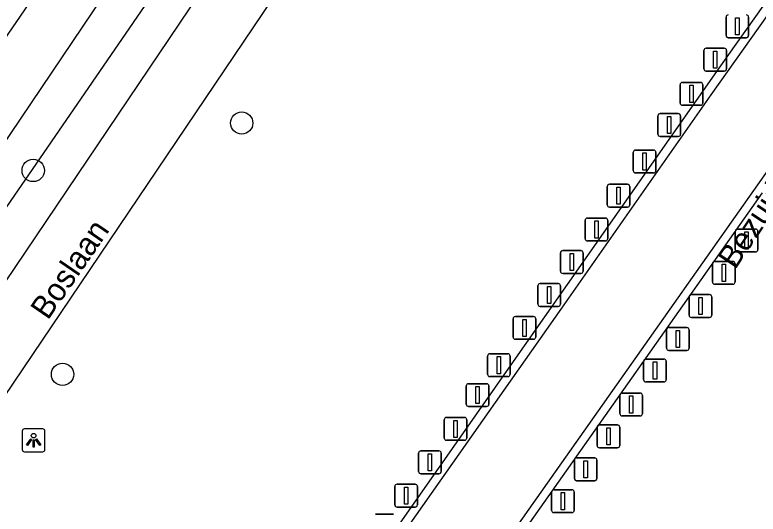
# Model space of a CAD drawing. Extents: x 157154 to 159278, y 385000 to 386650.
# Drawn here: x 159128.11 to 159160.66, y 385103.26 to 385125.13 of the extents above; entities that cross this region are included whole.
import ezdxf

# ---------------------------------------------------------------- set-up
doc = ezdxf.new("R2010")
doc.units = 0
for name, color, linetype in [('IMGEO_Afsluitpaal', 7, 'Continuous'), ('IMGEO_Boom', 7, 'Continuous'), ('IMGEO_Grasland_overig', 7, 'Continuous'), ('IMGEO_Lichtpunt', 7, 'Continuous'), ('IMGEO_Openbare_ruimte_label', 7, 'Continuous'), ('IMGEO_Rijbaan_lokaal_gesloten', 7, 'Continuous'), ('IMGEO_Rijbaan_lokaal_halfverhard', 7, 'Continuous'), ('IMGEO_Voetpad_halfverhard', 7, 'Continuous'), ('IMGEO_Waterloop', 7, 'Continuous')]:
    doc.layers.add(name, color=color, linetype=linetype)

msp = doc.modelspace()

# ---------------------------------------------------------------- linework, layer by layer
at = {"layer": 'IMGEO_Afsluitpaal'}
for p, q in [((159159.252, 385124.235), (159159.252, 385125.035)), ((159159.252, 385125.035), (159159.252, 385124.235)), ((159160.242, 385125.035), (159160.242, 385124.235)), ((159160.242, 385124.235), (159160.242, 385125.035)), ((159160.142, 385124.135), (159159.352, 385124.135)), ((159159.352, 385124.135), (159160.142, 385124.135)), ((159158.283, 385122.773), (159158.283, 385123.573)), ((159158.283, 385123.573), (159158.283, 385122.773)), ((159158.383, 385123.673), (159159.173, 385123.673)), ((159159.173, 385123.673), (159158.383, 385123.673)), ((159159.273, 385123.573), (159159.273, 385122.773)), ((159159.273, 385122.773), (159159.273, 385123.573)), ((159159.173, 385122.673), (159158.383, 385122.673)), ((159158.383, 385122.673), (159159.173, 385122.673)), ((159157.339, 385122.173), (159158.129, 385122.173)), ((159158.129, 385122.173), (159157.339, 385122.173)), ((159157.239, 385121.273), (159157.239, 385122.073)), ((159157.239, 385122.073), (159157.239, 385121.273)), ((159158.229, 385122.073), (159158.229, 385121.273)), ((159158.229, 385121.273), (159158.229, 385122.073)), ((159158.129, 385121.173), (159157.339, 385121.173)), ((159157.339, 385121.173), (159158.129, 385121.173)), ((159156.271, 385119.906), (159156.271, 385120.706)), ((159156.271, 385120.706), (159156.271, 385119.906)), ((159156.371, 385120.806), (159157.161, 385120.806)), ((159157.161, 385120.806), (159156.371, 385120.806)), ((159157.261, 385120.706), (159157.261, 385119.906)), ((159157.261, 385119.906), (159157.261, 385120.706)), ((159157.161, 385119.806), (159156.371, 385119.806)), ((159156.371, 385119.806), (159157.161, 385119.806)), ((159155.188, 385118.311), (159155.188, 385119.111)), ((159155.188, 385119.111), (159155.188, 385118.311)), ((159155.288, 385119.211), (159156.078, 385119.211)), ((159156.078, 385119.211), (159155.288, 385119.211)), ((159156.178, 385119.111), (159156.178, 385118.311)), ((159156.178, 385118.311), (159156.178, 385119.111)), ((159156.078, 385118.211), (159155.288, 385118.211)), ((159155.288, 385118.211), (159156.078, 385118.211)), ((159154.049, 385116.811), (159154.049, 385117.611)), ((159154.049, 385117.611), (159154.049, 385116.811)), ((159154.149, 385117.711), (159154.939, 385117.711)), ((159154.939, 385117.711), (159154.149, 385117.711)), ((159155.039, 385117.611), (159155.039, 385116.811)), ((159155.039, 385116.811), (159155.039, 385117.611)), ((159154.939, 385116.711), (159154.149, 385116.711)), ((159154.149, 385116.711), (159154.939, 385116.711)), ((159153.081, 385115.33), (159153.081, 385116.13)), ((159153.081, 385116.13), (159153.081, 385115.33)), ((159153.181, 385116.23), (159153.971, 385116.23)), ((159153.971, 385116.23), (159153.181, 385116.23)), ((159154.071, 385116.13), (159154.071, 385115.33)), ((159154.071, 385115.33), (159154.071, 385116.13)), ((159159.656, 385114.848), (159159.656, 385115.648)), ((159159.656, 385115.648), (159159.656, 385114.848)), ((159159.756, 385115.748), (159160.546, 385115.748)), ((159160.546, 385115.748), (159159.756, 385115.748)), ((159160.646, 385115.648), (159160.646, 385114.848)), ((159160.646, 385114.848), (159160.646, 385115.648)), ((159153.971, 385115.23), (159153.181, 385115.23)), ((159153.181, 385115.23), (159153.971, 385115.23)), ((159151.999, 385113.906), (159151.999, 385114.706)), ((159151.999, 385114.706), (159151.999, 385113.906)), ((159152.099, 385114.806), (159152.889, 385114.806)), ((159152.889, 385114.806), (159152.099, 385114.806)), ((159152.989, 385114.706), (159152.989, 385113.906)), ((159152.989, 385113.906), (159152.989, 385114.706)), ((159160.546, 385114.748), (159159.756, 385114.748)), ((159159.756, 385114.748), (159160.546, 385114.748)), ((159158.658, 385113.432), (159158.658, 385114.232)), ((159158.658, 385114.232), (159158.658, 385113.432)), ((159158.758, 385114.332), (159159.548, 385114.332)), ((159159.548, 385114.332), (159158.758, 385114.332)), ((159159.648, 385114.232), (159159.648, 385113.432)), ((159159.648, 385113.432), (159159.648, 385114.232)), ((159152.889, 385113.806), (159152.099, 385113.806)), ((159152.099, 385113.806), (159152.889, 385113.806)), ((159151.011, 385112.463), (159151.011, 385113.263)), ((159151.011, 385113.263), (159151.011, 385112.463)), ((159151.111, 385113.363), (159151.901, 385113.363)), ((159151.901, 385113.363), (159151.111, 385113.363)), ((159152.001, 385113.263), (159152.001, 385112.463)), ((159152.001, 385112.463), (159152.001, 385113.263)), ((159159.548, 385113.332), (159158.758, 385113.332)), ((159158.758, 385113.332), (159159.548, 385113.332)), ((159157.635, 385111.977), (159157.635, 385112.777)), ((159157.635, 385112.777), (159157.635, 385111.977)), ((159157.735, 385112.877), (159158.525, 385112.877)), ((159158.525, 385112.877), (159157.735, 385112.877)), ((159158.625, 385112.777), (159158.625, 385111.977)), ((159158.625, 385111.977), (159158.625, 385112.777)), ((159151.901, 385112.363), (159151.111, 385112.363)), ((159151.111, 385112.363), (159151.901, 385112.363)), ((159149.929, 385111.02), (159149.929, 385111.82)), ((159149.929, 385111.82), (159149.929, 385111.02)), ((159150.029, 385111.92), (159150.819, 385111.92)), ((159150.819, 385111.92), (159150.029, 385111.92)), ((159150.919, 385111.82), (159150.919, 385111.02)), ((159150.919, 385111.02), (159150.919, 385111.82)), ((159158.525, 385111.877), (159157.735, 385111.877)), ((159157.735, 385111.877), (159158.525, 385111.877)), ((159156.746, 385111.433), (159157.536, 385111.433)), ((159157.536, 385111.433), (159156.746, 385111.433)), ((159156.646, 385110.533), (159156.646, 385111.333)), ((159156.646, 385111.333), (159156.646, 385110.533)), ((159157.636, 385111.333), (159157.636, 385110.533)), ((159157.636, 385110.533), (159157.636, 385111.333)), ((159150.819, 385110.92), (159150.029, 385110.92)), ((159150.029, 385110.92), (159150.819, 385110.92)), ((159148.809, 385109.387), (159148.809, 385110.187)), ((159148.809, 385110.187), (159148.809, 385109.387)), ((159148.909, 385110.287), (159149.699, 385110.287)), ((159149.699, 385110.287), (159148.909, 385110.287)), ((159149.799, 385110.187), (159149.799, 385109.387)), ((159149.799, 385109.387), (159149.799, 385110.187)), ((159157.536, 385110.433), (159156.746, 385110.433)), ((159156.746, 385110.433), (159157.536, 385110.433)), ((159155.644, 385109.156), (159155.644, 385109.956)), ((159155.644, 385109.956), (159155.644, 385109.156)), ((159155.744, 385110.056), (159156.534, 385110.056)), ((159156.534, 385110.056), (159155.744, 385110.056)), ((159156.634, 385109.956), (159156.634, 385109.156)), ((159156.634, 385109.156), (159156.634, 385109.956)), ((159149.699, 385109.287), (159148.909, 385109.287)), ((159148.909, 385109.287), (159149.699, 385109.287)), ((159147.878, 385108.077), (159147.878, 385108.877)), ((159147.878, 385108.877), (159147.878, 385108.077)), ((159147.978, 385108.977), (159148.768, 385108.977)), ((159148.768, 385108.977), (159147.978, 385108.977)), ((159148.868, 385108.877), (159148.868, 385108.077)), ((159148.868, 385108.077), (159148.868, 385108.877)), ((159156.534, 385109.056), (159155.744, 385109.056)), ((159155.744, 385109.056), (159156.534, 385109.056)), ((159154.704, 385108.565), (159155.494, 385108.565)), ((159155.494, 385108.565), (159154.704, 385108.565)), ((159154.604, 385107.665), (159154.604, 385108.465)), ((159154.604, 385108.465), (159154.604, 385107.665)), ((159155.594, 385108.465), (159155.594, 385107.665)), ((159155.594, 385107.665), (159155.594, 385108.465)), ((159148.768, 385107.977), (159147.978, 385107.977)), ((159147.978, 385107.977), (159148.768, 385107.977)), ((159155.494, 385107.565), (159154.704, 385107.565)), ((159154.704, 385107.565), (159155.494, 385107.565)), ((159146.91, 385106.596), (159146.91, 385107.396)), ((159146.91, 385107.396), (159146.91, 385106.596)), ((159147.01, 385107.496), (159147.8, 385107.496)), ((159147.8, 385107.496), (159147.01, 385107.496)), ((159147.9, 385107.396), (159147.9, 385106.596)), ((159147.9, 385106.596), (159147.9, 385107.396)), ((159153.605, 385106.268), (159153.605, 385107.068)), ((159153.605, 385107.068), (159153.605, 385106.268)), ((159153.705, 385107.168), (159154.495, 385107.168)), ((159154.495, 385107.168), (159153.705, 385107.168)), ((159154.595, 385107.068), (159154.595, 385106.268)), ((159154.595, 385106.268), (159154.595, 385107.068)), ((159147.8, 385106.496), (159147.01, 385106.496)), ((159147.01, 385106.496), (159147.8, 385106.496)), ((159145.79, 385105.134), (159145.79, 385105.934)), ((159145.79, 385105.934), (159145.79, 385105.134)), ((159145.89, 385106.034), (159146.68, 385106.034)), ((159146.68, 385106.034), (159145.89, 385106.034)), ((159146.78, 385105.934), (159146.78, 385105.134)), ((159146.78, 385105.134), (159146.78, 385105.934)), ((159154.495, 385106.168), (159153.705, 385106.168)), ((159153.705, 385106.168), (159154.495, 385106.168)), ((159152.61, 385104.827), (159152.61, 385105.627)), ((159152.61, 385105.627), (159152.61, 385104.827)), ((159152.71, 385105.727), (159153.5, 385105.727)), ((159153.5, 385105.727), (159152.71, 385105.727)), ((159153.6, 385105.627), (159153.6, 385104.827)), ((159153.6, 385104.827), (159153.6, 385105.627)), ((159146.68, 385105.034), (159145.89, 385105.034)), ((159145.89, 385105.034), (159146.68, 385105.034)), ((159153.5, 385104.727), (159152.71, 385104.727)), ((159152.71, 385104.727), (159153.5, 385104.727)), ((159144.745, 385103.672), (159144.745, 385104.472)), ((159144.745, 385104.472), (159144.745, 385103.672)), ((159144.845, 385104.572), (159145.635, 385104.572)), ((159145.635, 385104.572), (159144.845, 385104.572)), ((159145.735, 385104.472), (159145.735, 385103.672)), ((159145.735, 385103.672), (159145.735, 385104.472)), ((159151.713, 385104.328), (159152.503, 385104.328)), ((159152.503, 385104.328), (159151.713, 385104.328)), ((159151.613, 385103.428), (159151.613, 385104.228)), ((159151.613, 385104.228), (159151.613, 385103.428)), ((159152.603, 385104.228), (159152.603, 385103.428)), ((159152.603, 385103.428), (159152.603, 385104.228)), ((159145.635, 385103.572), (159144.845, 385103.572)), ((159144.845, 385103.572), (159145.635, 385103.572)), ((159152.503, 385103.328), (159151.713, 385103.328)), ((159151.713, 385103.328), (159152.503, 385103.328)), ((159143.896, 385103.262), (159144.686, 385103.262)), ((159144.686, 385103.262), (159143.896, 385103.262))]:
    msp.add_line(p, q, dxfattribs=at)
for points in [[(159159.672, 385125.01), (159159.822, 385125.01), (159159.822, 385124.26), (159159.672, 385124.26), (159159.672, 385125.01)], [(159158.703, 385123.548), (159158.853, 385123.548), (159158.853, 385122.798), (159158.703, 385122.798), (159158.703, 385123.548)], [(159157.659, 385122.048), (159157.809, 385122.048), (159157.809, 385121.298), (159157.659, 385121.298), (159157.659, 385122.048)], [(159156.691, 385120.681), (159156.841, 385120.681), (159156.841, 385119.931), (159156.691, 385119.931), (159156.691, 385120.681)], [(159155.608, 385119.086), (159155.758, 385119.086), (159155.758, 385118.336), (159155.608, 385118.336), (159155.608, 385119.086)], [(159154.469, 385117.586), (159154.619, 385117.586), (159154.619, 385116.836), (159154.469, 385116.836), (159154.469, 385117.586)], [(159153.501, 385116.105), (159153.651, 385116.105), (159153.651, 385115.355), (159153.501, 385115.355), (159153.501, 385116.105)], [(159160.076, 385115.623), (159160.226, 385115.623), (159160.226, 385114.873), (159160.076, 385114.873), (159160.076, 385115.623)], [(159152.419, 385114.681), (159152.569, 385114.681), (159152.569, 385113.931), (159152.419, 385113.931), (159152.419, 385114.681)], [(159159.078, 385114.207), (159159.228, 385114.207), (159159.228, 385113.457), (159159.078, 385113.457), (159159.078, 385114.207)], [(159151.431, 385113.238), (159151.581, 385113.238), (159151.581, 385112.488), (159151.431, 385112.488), (159151.431, 385113.238)], [(159158.055, 385112.752), (159158.205, 385112.752), (159158.205, 385112.002), (159158.055, 385112.002), (159158.055, 385112.752)], [(159150.349, 385111.795), (159150.499, 385111.795), (159150.499, 385111.045), (159150.349, 385111.045), (159150.349, 385111.795)], [(159157.066, 385111.308), (159157.216, 385111.308), (159157.216, 385110.558), (159157.066, 385110.558), (159157.066, 385111.308)], [(159149.229, 385110.162), (159149.379, 385110.162), (159149.379, 385109.412), (159149.229, 385109.412), (159149.229, 385110.162)], [(159156.064, 385109.931), (159156.214, 385109.931), (159156.214, 385109.181), (159156.064, 385109.181), (159156.064, 385109.931)], [(159148.298, 385108.852), (159148.448, 385108.852), (159148.448, 385108.102), (159148.298, 385108.102), (159148.298, 385108.852)], [(159155.024, 385108.44), (159155.174, 385108.44), (159155.174, 385107.69), (159155.024, 385107.69), (159155.024, 385108.44)], [(159147.33, 385107.371), (159147.48, 385107.371), (159147.48, 385106.621), (159147.33, 385106.621), (159147.33, 385107.371)], [(159154.025, 385107.043), (159154.175, 385107.043), (159154.175, 385106.293), (159154.025, 385106.293), (159154.025, 385107.043)], [(159146.21, 385105.909), (159146.36, 385105.909), (159146.36, 385105.159), (159146.21, 385105.159), (159146.21, 385105.909)], [(159153.03, 385105.602), (159153.18, 385105.602), (159153.18, 385104.852), (159153.03, 385104.852), (159153.03, 385105.602)], [(159145.165, 385104.447), (159145.315, 385104.447), (159145.315, 385103.697), (159145.165, 385103.697), (159145.165, 385104.447)], [(159152.033, 385104.203), (159152.183, 385104.203), (159152.183, 385103.453), (159152.033, 385103.453), (159152.033, 385104.203)]]:
    msp.add_lwpolyline(points, dxfattribs=at)
for centre, start, end in [((159159.352, 385125.035), 90, 180), ((159159.352, 385125.035), 90, 180), ((159160.142, 385125.035), 0, 90), ((159160.142, 385125.035), 360, 90), ((159159.352, 385124.235), 180, 270), ((159159.352, 385124.235), 180, 270), ((159160.142, 385124.235), 270, 0), ((159160.142, 385124.235), 270, 0), ((159158.383, 385123.573), 90, 180), ((159158.383, 385123.573), 90, 180), ((159159.173, 385123.573), 0, 90), ((159159.173, 385123.573), 360, 90), ((159158.383, 385122.773), 180, 270), ((159158.383, 385122.773), 180, 270), ((159159.173, 385122.773), 270, 0), ((159159.173, 385122.773), 270, 0), ((159157.339, 385122.073), 90, 180), ((159157.339, 385122.073), 90, 180), ((159158.129, 385122.073), 0, 90), ((159158.129, 385122.073), 360, 90), ((159157.339, 385121.273), 180, 270), ((159157.339, 385121.273), 180, 270), ((159158.129, 385121.273), 270, 0), ((159158.129, 385121.273), 270, 0), ((159156.371, 385120.706), 90, 180), ((159156.371, 385120.706), 90, 180), ((159157.161, 385120.706), 0, 90), ((159157.161, 385120.706), 360, 90), ((159156.371, 385119.906), 180, 270), ((159156.371, 385119.906), 180, 270), ((159157.161, 385119.906), 270, 0), ((159157.161, 385119.906), 270, 0), ((159155.288, 385119.111), 90, 180), ((159155.288, 385119.111), 90, 180), ((159156.078, 385119.111), 0, 90), ((159156.078, 385119.111), 360, 90), ((159155.288, 385118.311), 180, 270), ((159155.288, 385118.311), 180, 270), ((159156.078, 385118.311), 270, 0), ((159156.078, 385118.311), 270, 0), ((159154.149, 385117.611), 90, 180), ((159154.149, 385117.611), 90, 180), ((159154.939, 385117.611), 0, 90), ((159154.939, 385117.611), 360, 90), ((159154.149, 385116.811), 180, 270), ((159154.149, 385116.811), 180, 270), ((159154.939, 385116.811), 270, 0), ((159154.939, 385116.811), 270, 0), ((159153.181, 385116.13), 90, 180), ((159153.181, 385116.13), 90, 180), ((159153.971, 385116.13), 0, 90), ((159153.971, 385116.13), 360, 90), ((159159.756, 385115.648), 90, 180), ((159159.756, 385115.648), 90, 180), ((159160.546, 385115.648), 0, 90), ((159160.546, 385115.648), 360, 90), ((159153.181, 385115.33), 180, 270), ((159153.181, 385115.33), 180, 270), ((159153.971, 385115.33), 270, 0), ((159153.971, 385115.33), 270, 0), ((159152.099, 385114.706), 90, 180), ((159152.099, 385114.706), 90, 180), ((159152.889, 385114.706), 0, 90), ((159152.889, 385114.706), 360, 90), ((159159.756, 385114.848), 180, 270), ((159159.756, 385114.848), 180, 270), ((159160.546, 385114.848), 270, 0), ((159160.546, 385114.848), 270, 0), ((159158.758, 385114.232), 90, 180), ((159158.758, 385114.232), 90, 180), ((159159.548, 385114.232), 0, 90), ((159159.548, 385114.232), 360, 90), ((159152.099, 385113.906), 180, 270), ((159152.099, 385113.906), 180, 270), ((159152.889, 385113.906), 270, 0), ((159152.889, 385113.906), 270, 0), ((159158.758, 385113.432), 180, 270), ((159158.758, 385113.432), 180, 270), ((159159.548, 385113.432), 270, 0), ((159159.548, 385113.432), 270, 0), ((159151.111, 385113.263), 90, 180), ((159151.111, 385113.263), 90, 180), ((159151.901, 385113.263), 0, 90), ((159151.901, 385113.263), 360, 90), ((159157.735, 385112.777), 90, 180), ((159157.735, 385112.777), 90, 180), ((159158.525, 385112.777), 0, 90), ((159158.525, 385112.777), 360, 90), ((159151.111, 385112.463), 180, 270), ((159151.111, 385112.463), 180, 270), ((159151.901, 385112.463), 270, 0), ((159151.901, 385112.463), 270, 0), ((159150.029, 385111.82), 90, 180), ((159150.029, 385111.82), 90, 180), ((159150.819, 385111.82), 0, 90), ((159150.819, 385111.82), 360, 90), ((159157.735, 385111.977), 180, 270), ((159157.735, 385111.977), 180, 270), ((159158.525, 385111.977), 270, 0), ((159158.525, 385111.977), 270, 0), ((159156.746, 385111.333), 90, 180), ((159156.746, 385111.333), 90, 180), ((159157.536, 385111.333), 0, 90), ((159157.536, 385111.333), 360, 90), ((159150.029, 385111.02), 180, 270), ((159150.029, 385111.02), 180, 270), ((159150.819, 385111.02), 270, 0), ((159150.819, 385111.02), 270, 0), ((159156.746, 385110.533), 180, 270), ((159156.746, 385110.533), 180, 270), ((159157.536, 385110.533), 270, 0), ((159157.536, 385110.533), 270, 0), ((159148.909, 385110.187), 90, 180), ((159148.909, 385110.187), 90, 180), ((159149.699, 385110.187), 0, 90), ((159149.699, 385110.187), 360, 90), ((159155.744, 385109.956), 90, 180), ((159155.744, 385109.956), 90, 180), ((159156.534, 385109.956), 0, 90), ((159156.534, 385109.956), 360, 90), ((159148.909, 385109.387), 180, 270), ((159148.909, 385109.387), 180, 270), ((159149.699, 385109.387), 270, 0), ((159149.699, 385109.387), 270, 0), ((159155.744, 385109.156), 180, 270), ((159155.744, 385109.156), 180, 270), ((159156.534, 385109.156), 270, 0), ((159156.534, 385109.156), 270, 0), ((159147.978, 385108.877), 90, 180), ((159147.978, 385108.877), 90, 180), ((159148.768, 385108.877), 0, 90), ((159148.768, 385108.877), 360, 90), ((159154.704, 385108.465), 90, 180), ((159154.704, 385108.465), 90, 180), ((159155.494, 385108.465), 0, 90), ((159155.494, 385108.465), 360, 90), ((159147.978, 385108.077), 180, 270), ((159147.978, 385108.077), 180, 270), ((159148.768, 385108.077), 270, 0), ((159148.768, 385108.077), 270, 0), ((159154.704, 385107.665), 180, 270), ((159154.704, 385107.665), 180, 270), ((159155.494, 385107.665), 270, 0), ((159155.494, 385107.665), 270, 0), ((159147.01, 385107.396), 90, 180), ((159147.01, 385107.396), 90, 180), ((159147.8, 385107.396), 0, 90), ((159147.8, 385107.396), 360, 90), ((159153.705, 385107.068), 90, 180), ((159153.705, 385107.068), 90, 180), ((159154.495, 385107.068), 0, 90), ((159154.495, 385107.068), 360, 90), ((159147.01, 385106.596), 180, 270), ((159147.01, 385106.596), 180, 270), ((159147.8, 385106.596), 270, 0), ((159147.8, 385106.596), 270, 0), ((159153.705, 385106.268), 180, 270), ((159153.705, 385106.268), 180, 270), ((159154.495, 385106.268), 270, 0), ((159154.495, 385106.268), 270, 0), ((159145.89, 385105.934), 90, 180), ((159145.89, 385105.934), 90, 180), ((159146.68, 385105.934), 0, 90), ((159146.68, 385105.934), 360, 90), ((159152.71, 385105.627), 90, 180), ((159152.71, 385105.627), 90, 180), ((159153.5, 385105.627), 0, 90), ((159153.5, 385105.627), 360, 90), ((159145.89, 385105.134), 180, 270), ((159145.89, 385105.134), 180, 270), ((159146.68, 385105.134), 270, 0), ((159146.68, 385105.134), 270, 0), ((159152.71, 385104.827), 180, 270), ((159152.71, 385104.827), 180, 270), ((159153.5, 385104.827), 270, 0), ((159153.5, 385104.827), 270, 0), ((159144.845, 385104.472), 90, 180), ((159144.845, 385104.472), 90, 180), ((159145.635, 385104.472), 0, 90), ((159145.635, 385104.472), 360, 90), ((159151.713, 385104.228), 90, 180), ((159151.713, 385104.228), 90, 180), ((159152.503, 385104.228), 0, 90), ((159152.503, 385104.228), 360, 90), ((159144.845, 385103.672), 180, 270), ((159144.845, 385103.672), 180, 270), ((159145.635, 385103.672), 270, 0), ((159145.635, 385103.672), 270, 0), ((159151.713, 385103.428), 180, 270), ((159151.713, 385103.428), 180, 270), ((159152.503, 385103.428), 270, 0), ((159152.503, 385103.428), 270, 0)]:
    msp.add_arc(centre, 0.1, start, end, dxfattribs=at)
at = {"layer": 'IMGEO_Boom'}
for centre in [(159138.044, 385120.396), (159128.913, 385118.319), (159130.199, 385109.386)]:
    msp.add_circle(centre, 0.489, dxfattribs=at)
at = {"layer": 'IMGEO_Grasland_overig'}
msp.add_lwpolyline([(159079.233, 385045.507), (159095.149, 385068.441), (159122.513, 385109.122), (159136.9, 385130.044), (159158.739, 385162.357), (159177.304, 385190.183)], dxfattribs=at)
at = {"layer": 'IMGEO_Lichtpunt'}
for p, q in [((159128.432, 385106.899), (159128.432, 385106.092)), ((159128.432, 385106.899), (159128.432, 385106.092)), ((159129.334, 385106.994), (159128.526, 385106.994)), ((159129.334, 385106.994), (159128.526, 385106.994)), ((159129.428, 385106.092), (159129.428, 385106.899)), ((159129.428, 385106.092), (159129.428, 385106.899)), ((159128.526, 385105.998), (159129.334, 385105.998)), ((159128.526, 385105.998), (159129.334, 385105.998))]:
    msp.add_line(p, q, dxfattribs=at)
for points in [[(159128.806, 385106.563), (159128.845, 385106.535), (159128.657, 385106.273), (159128.619, 385106.3), (159128.806, 385106.563)], [(159129.018, 385106.535), (159129.056, 385106.562), (159129.243, 385106.3), (159129.204, 385106.272), (159129.018, 385106.535)], [(159128.908, 385106.515), (159128.955, 385106.515), (159128.955, 385106.193), (159128.908, 385106.193), (159128.908, 385106.515)]]:
    msp.add_lwpolyline(points, dxfattribs=at)
msp.add_circle((159128.931, 385106.697), 0.0994, dxfattribs=at)
for centre, start, end in [((159128.526, 385106.899), 90, 180), ((159128.526, 385106.899), 90, 180), ((159129.334, 385106.899), 0, 90), ((159129.334, 385106.899), 0, 90), ((159128.526, 385106.092), 180, 270), ((159128.526, 385106.092), 180, 270), ((159129.334, 385106.092), 270, 0), ((159129.334, 385106.092), 270, 360)]:
    msp.add_arc(centre, 0.0946, start, end, dxfattribs=at)
at = {"layer": 'IMGEO_Rijbaan_lokaal_gesloten'}
for points in [[(159193.211, 385168.845), (159187.56, 385161.643), (159181.331, 385153.165), (159172.644, 385141.459), (159166.702, 385133.073), (159158.593, 385121.626), (159152.041, 385112.291), (159143.441, 385100.038), (159135.503, 385088.629), (159130.039, 385080.599), (159124.39, 385072.298), (159120.076, 385065.821), (159112.721, 385054.945), (159108.114, 385048.109), (159097.939, 385033.062), (159087.928, 385018.043), (159086.779, 385016.337), (159085.933, 385015.081), (159084.062, 385012.304), (159080.634, 385007.363), (159077.549, 385002.725)], [(159080.766, 385000.498), (159084.558, 385006.205), (159091.41, 385016.362), (159101.183, 385030.766), (159107.116, 385039.583), (159113.235, 385048.651), (159133.732, 385079.03), (159149.547, 385101.952), (159165.213, 385124.168), (159173.703, 385136.301), (159179.735, 385144.683), (159187.963, 385155.555)]]:
    msp.add_lwpolyline(points, dxfattribs=at)
at = {"layer": 'IMGEO_Rijbaan_lokaal_halfverhard'}
for points in [[(159205.897, 385185.21), (159204.63, 385183.767), (159204.056, 385183.113), (159203.242, 385182.186), (159198.852, 385176.747), (159187.24, 385161.886), (159172.319, 385141.694), (159166.375, 385133.305), (159159.356, 385123.396), (159158.832, 385122.656), (159142.886, 385099.88), (159126.391, 385075.847), (159107.34, 385047.66), (159091.697, 385024.574), (159087.555, 385018.32)], [(159160.83, 385117.337), (159149.838, 385101.749), (159145.304, 385095.179)]]:
    msp.add_lwpolyline(points, dxfattribs=at)
at = {"layer": 'IMGEO_Voetpad_halfverhard'}
for points in [[(159202.762, 385214.209), (159200.279, 385212.099), (159197.861, 385209.917), (159197.685, 385209.729), (159188.555, 385198.998), (159187.341, 385197.178), (159184.592, 385192.9), (159180.472, 385186.763), (159159.585, 385155.808), (159126.749, 385107.119), (159084.716, 385044.777), (159082.453, 385041.511)], [(159079.888, 385042.589), (159124.552, 385108.774), (159157.303, 385157.398), (159178.092, 385188.144), (159178.542, 385188.806)]]:
    msp.add_lwpolyline(points, dxfattribs=at)
at = {"layer": 'IMGEO_Waterloop'}
for points in [[(159174.39, 385188.362), (159156.453, 385163.154), (159141.401, 385139.978), (159122.96, 385112.597), (159097.748, 385075.847), (159079.166, 385046.919), (159078.814, 385046.638), (159078.374, 385046.564), (159076.434, 385047.649), (159076.208, 385048.03), (159076.204, 385048.403), (159076.336, 385048.723), (159076.94, 385049.624)], [(159076.94, 385049.624), (159088.077, 385066.264), (159104.504, 385090.052), (159123.462, 385117.952), (159132.885, 385131.714), (159147.66, 385153.943), (159156.778, 385167.227)]]:
    msp.add_lwpolyline(points, dxfattribs=at)

# ---------------------------------------------------------------- texts
at = {"layer": 'IMGEO_Openbare_ruimte_label'}
for s, rotation, p in [('Bezuidenhoutseweg', 56.2146, (159159.65, 385113.948)), ('Boslaan', 55.5948, (159129.555, 385111.728))]:
    msp.add_text(s, height=1, rotation=rotation, dxfattribs=at).set_placement(p)

doc.saveas('drawing.dxf')
